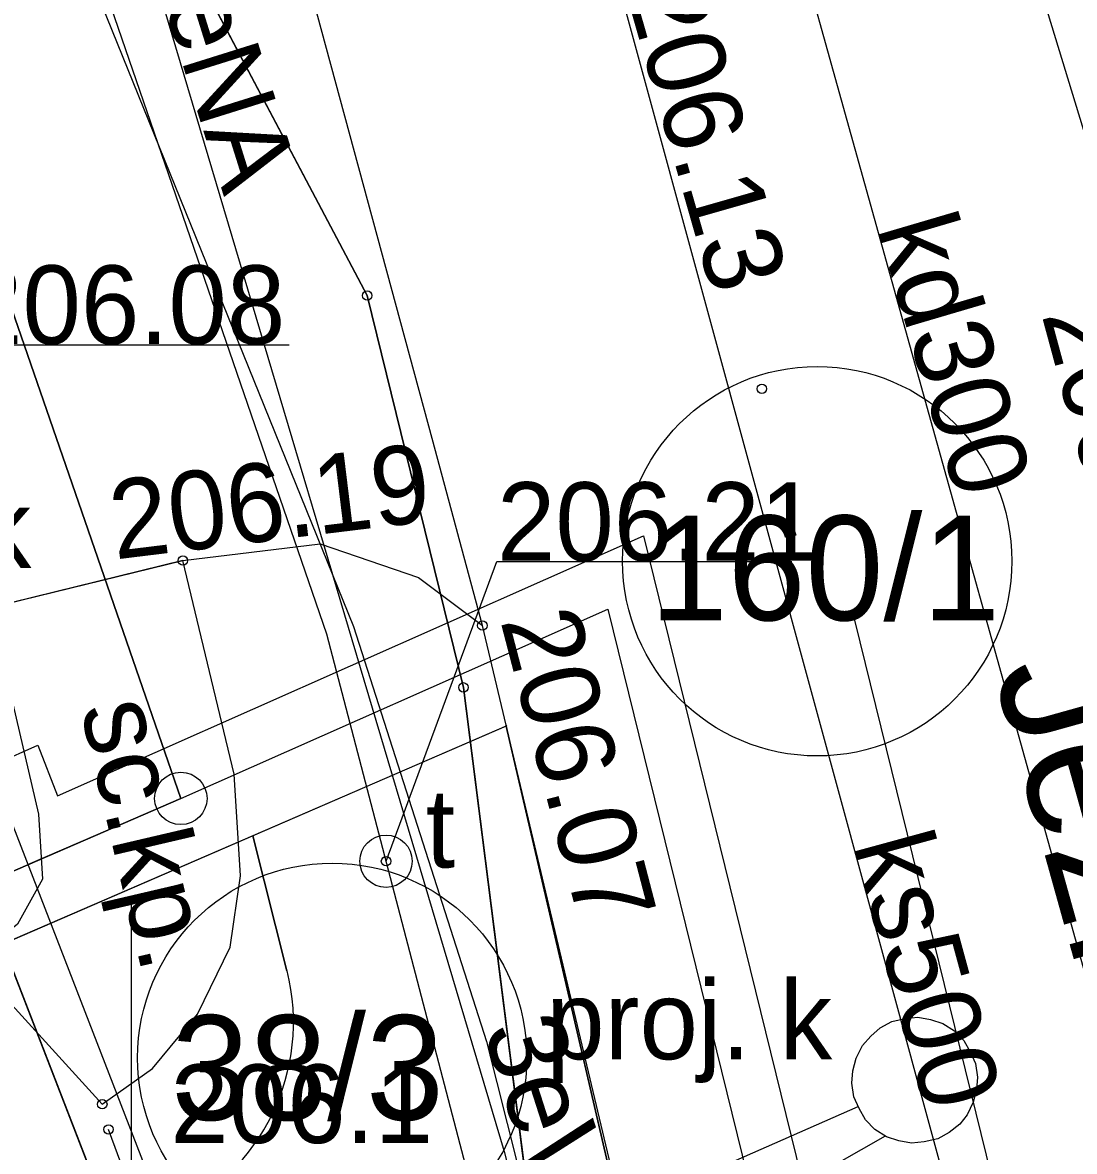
# Model space of a CAD drawing. Extents: x 6512606 to 6513006, y 6022524 to 6022728.
# Drawn here: x 6512848.96 to 6512859.01, y 6022600.08 to 6022610.86 of the extents above; entities that cross this region are included whole.
import ezdxf

# ---------------------------------------------------------------- set-up
doc = ezdxf.new("R2010")
doc.units = 0
for name, color, linetype in [('202-punkt graniczny', 7, 'Continuous'), ('203-punkt graniczny', 7, 'Continuous'), ('211-numer działki ewidencyjnej', 7, 'Continuous'), ('216-obręb ewidencyjny', 7, 'Continuous'), ('217-kontur klasyfikacyjny', 7, 'Continuous'), ('218-kontur użytku gruntowego', 7, 'Continuous'), ('219-działka ewidencyjna', 7, 'Continuous'), ('4', 7, 'Continuous'), ('6', 7, 'Continuous'), ('994-Nazwa ulicy', 7, 'Continuous'), ('Default', 7, 'Continuous'), ('jezdnia (powierzchnia)', 7, 'Continuous'), ('kolor_chodnik', 7, 'Continuous'), ('kolor_sc_rowerowa', 7, 'Continuous'), ('krawężnik (linia)', 7, 'Continuous'), ('maxp_kan_deszczowa', 7, 'Continuous'), ('maxp_kraw_nawierzchni', 7, 'Continuous'), ('maxp_os', 7, 'Continuous'), ('maxp_ramka_2', 7, 'Continuous'), ('ogrodzenie trwałe', 7, 'Continuous'), ('pikieta naturalna', 7, 'Continuous'), ('pikieta naturalna-Atr2', 7, 'Continuous'), ('pikieta sztuczna', 7, 'Continuous'), ('przewód elektroenergetyczny (linia)', 7, 'Continuous'), ('przewód elektroenergetyczny (linia)-Atr1', 7, 'Continuous'), ('przewód kanalizacyjny (linia)', 7, 'Continuous'), ('przewód kanalizacyjny (linia)-Atr1', 7, 'Continuous'), ('przewód kanalizacyjny - projektowany lub w budowie (linia) - ob. projektowany', 7, 'Continuous'), ('przewód telekomunikacyjny (linia)', 7, 'Continuous'), ('przewód wodociągowy (linia)', 7, 'Continuous'), ('punkt o określonej wysokości (sieć kanalizacyjna)-Atr2', 7, 'Continuous'), ('punkt o określonej wysokości (sieć telekomunikacyjna)', 7, 'Continuous'), ('punkt o określonej wysokości (sieć telekomunikacyjna)-Atr2', 7, 'Continuous'), ('punkt wysokościowy sztuczny', 7, 'Continuous'), ('punkt wysokościowy sztuczny-Atr2', 7, 'Continuous'), ('urządzenie techniczne projektowane lub w budowie (sieć kanalizacyjna) - powierzchnia - ob. projektowany', 7, 'Continuous'), ('urządzenie techniczne projektowane lub w budowie (sieć kanalizacyjna) - powierzchnia - ob. projektowany-Atr17', 7, 'Continuous'), ('właz okrągły - siec kanalizacyjna (punkt)-Atr17', 7, 'Continuous'), ('właz okrągły - siec telekomunikacyjna (punkt)', 7, 'Continuous'), ('właz okrągły - siec telekomunikacyjna (punkt)-Atr17', 7, 'Continuous'), ('ścieżka (powierzchnia)', 7, 'Continuous'), ('ścieżka (powierzchnia)-Atr17', 7, 'Continuous')]:
    doc.layers.add(name, color=color, linetype=linetype)

# ---------------------------------------------------------------- blocks, each defined once
blk = doc.blocks.new('203')
at = {"layer": 'Default'}
blk.add_circle((0, 0), 0.45, dxfattribs=at)
blk = doc.blocks.new('202')
at = {"layer": 'Default'}
blk.add_circle((0, 0), 2.5, dxfattribs=at)
blk = doc.blocks.new('US22')
at = {"layer": 'Default'}
blk.add_circle((0, 0), 2.5, dxfattribs=at)
blk = doc.blocks.new('PW01')
at = {"layer": 'Default'}
blk.add_circle((0, 0), 0.45, dxfattribs=at)
blk = doc.blocks.new('PW02')
at = {"layer": 'Default'}
blk.add_circle((0, 0), 0.45, dxfattribs=at)

msp = doc.modelspace()

# ---------------------------------------------------------------- linework, layer by layer
at = {"layer": '216-obręb ewidencyjny'}
for points in [[(6512836.687, 6022675.173), (6512833.61, 6022675.02), (6512828.67, 6022670.98), (6512801.96, 6022670.34), (6512810.18, 6022663.28), (6512825.37, 6022649.66), (6512838.47, 6022634.29), (6512852.25, 6022608.25), (6512853.17, 6022604.51), (6512855.78, 6022583.95), (6512858.85, 6022571.74), (6512828.23, 6022562.62), (6512818.47, 6022559.72), (6512824.714, 6022553.406)], [(6512728.286, 6022540.131), (6512737.69, 6022552.74), (6512751.08, 6022569.37), (6512775.81, 6022564.08), (6512780.7, 6022581.02), (6512806.2, 6022572.11), (6512806.62, 6022563.51), (6512811.41, 6022558.95), (6512818.47, 6022559.72), (6512828.23, 6022562.62), (6512858.85, 6022571.74), (6512855.78, 6022583.95), (6512853.17, 6022604.51), (6512852.25, 6022608.25), (6512838.47, 6022634.29)]]:
    msp.add_lwpolyline(points, dxfattribs=at)
at = {"layer": '217-kontur klasyfikacyjny'}
msp.add_lwpolyline([(6512855.78, 6022583.95), (6512848.55, 6022602.62)], dxfattribs=at)
at = {"layer": '218-kontur użytku gruntowego'}
for points in [[(6512852.25, 6022608.25), (6512838.47, 6022634.29)], [(6512838.47, 6022634.29), (6512852.25, 6022608.25)], [(6512850.47, 6022603.45), (6512842.84, 6022625.52)], [(6512842.84, 6022625.52), (6512850.47, 6022603.45)], [(6512853.17, 6022604.51), (6512852.25, 6022608.25)], [(6512852.25, 6022608.25), (6512853.17, 6022604.51)], [(6512855.78, 6022583.95), (6512853.17, 6022604.51)], [(6512853.17, 6022604.51), (6512855.78, 6022583.95)], [(6512848.55, 6022602.62), (6512850.47, 6022603.45)], [(6512850.47, 6022603.45), (6512848.55, 6022602.62)], [(6512848.55, 6022602.62), (6512855.78, 6022583.95)], [(6512855.78, 6022583.95), (6512848.55, 6022602.62)]]:
    msp.add_lwpolyline(points, dxfattribs=at)
at = {"layer": '219-działka ewidencyjna'}
for points in [[(6512838.47, 6022634.29), (6512852.25, 6022608.25)], [(6512842.84, 6022625.52), (6512850.47, 6022603.45)], [(6512853.17, 6022604.51), (6512852.25, 6022608.25)], [(6512855.78, 6022583.95), (6512853.17, 6022604.51)], [(6512850.47, 6022603.45), (6512848.55, 6022602.62)], [(6512855.78, 6022583.95), (6512848.55, 6022602.62)]]:
    msp.add_lwpolyline(points, dxfattribs=at)
at = {"layer": '4'}
for points in [[(6512838.47, 6022634.29), (6512852.25, 6022608.25)], [(6512842.84, 6022625.52), (6512850.47, 6022603.45)], [(6512853.17, 6022604.51), (6512852.25, 6022608.25)], [(6512855.78, 6022583.95), (6512853.17, 6022604.51)], [(6512850.47, 6022603.45), (6512848.55, 6022602.62)], [(6512855.78, 6022583.95), (6512848.55, 6022602.62)]]:
    msp.add_lwpolyline(points, dxfattribs=at)
at = {"layer": '6'}
for centre in [(6512856.549, 6022605.714), (6512851.916, 6022600.973)]:
    msp.add_circle(centre, 1.859, dxfattribs=at)
at = {"layer": 'Default'}
msp.add_line((6512850, 6022597.5), (6512850, 6022602.5), dxfattribs=at)
at = {"layer": 'jezdnia (powierzchnia)'}
msp.add_lwpolyline([(6512850.75, 6022614.71), (6512850.26, 6022613.71), (6512849.8, 6022613.04), (6512849.09, 6022612.33), (6512848.25, 6022611.75), (6512847.02, 6022611.04), (6512845.61, 6022610.5), (6512847.59, 6022605.11), (6512848.64, 6022605.27), (6512850.49, 6022605.72), (6512851.8, 6022605.88), (6512852.74, 6022605.56), (6512853.35, 6022605.1), (6512852.88, 6022606.85)], close=True, dxfattribs=at)
at = {"layer": 'kolor_chodnik'}
for p, q in [((6512853.578, 6022604.141), (6512851.157, 6022603.094)), ((6512854.975, 6022598.118), (6512853.578, 6022604.141)), ((6512851.157, 6022603.094), (6512851.484, 6022601.804))]:
    msp.add_line(p, q, dxfattribs=at)
msp.add_arc((6512849.546, 6022601.311), 2, 293.9, 14.2544, dxfattribs=at)
at = {"layer": 'kolor_sc_rowerowa'}
for p, q in [((6512851.157, 6022603.094), (6512848.767, 6022602.06)), ((6512851.484, 6022601.804), (6512851.157, 6022603.094))]:
    msp.add_line(p, q, dxfattribs=at)
msp.add_arc((6512849.546, 6022601.311), 2, 293.9, 14.2544, dxfattribs=at)
at = {"layer": 'krawężnik (linia)'}
msp.add_lwpolyline([(6512858.01, 6022586.22), (6512857.23, 6022588.81), (6512855.05, 6022597.75), (6512854.71, 6022599.38), (6512853.35, 6022605.1)], dxfattribs=at)
at = {"layer": 'maxp_kan_deszczowa'}
msp.add_lwpolyline([(6512851.482, 6022595.049), (6512848.64, 6022602.387), (6512844.992, 6022600.824), (6512840.035, 6022598.38)], dxfattribs=at)
at = {"layer": 'maxp_kraw_nawierzchni'}
for p, q in [((6512848.767, 6022602.06), (6512853.586, 6022604.145)), ((6512853.578, 6022604.141), (6512854.975, 6022598.118)), ((6512851.157, 6022603.094), (6512851.484, 6022601.804))]:
    msp.add_line(p, q, dxfattribs=at)
msp.add_arc((6512849.546, 6022601.311), 2, 293.9, 14.2544, dxfattribs=at)
at = {"layer": 'maxp_os'}
msp.add_line((6512856.906, 6022605.15), (6512862.491, 6022582.465), dxfattribs=at)
at = {"layer": 'maxp_ramka_2'}
for p, q in [((6512849.291, 6022603.475), (6512854.891, 6022605.956)), ((6512854.891, 6022605.956), (6512860.654, 6022582.548)), ((6512850.47, 6022603.45), (6512854.549, 6022605.257)), ((6512854.549, 6022605.257), (6512860.068, 6022582.835)), ((6512819.784, 6022590.966), (6512849.104, 6022603.959)), ((6512849.104, 6022603.959), (6512849.291, 6022603.475)), ((6512848.827, 6022603.29), (6512856.423, 6022583.675))]:
    msp.add_line(p, q, dxfattribs=at)
msp.add_lwpolyline([(6512849.009, 6022602.819), (6512850.47, 6022603.45)], dxfattribs=at)
at = {"layer": 'ogrodzenie trwałe'}
msp.add_lwpolyline([(6512851.8, 6022594.83), (6512849.78, 6022600.29)], dxfattribs=at)
at = {"layer": 'przewód elektroenergetyczny (linia)'}
for points in [[(6512802.27, 6022673.66), (6512807.42, 6022670.09), (6512811.38, 6022666.87), (6512814.66, 6022663.43), (6512826.4, 6022651.65), (6512827.82, 6022650.09), (6512834.03, 6022642.46), (6512842.84, 6022631.19), (6512844.67, 6022626.95), (6512847.57, 6022619.87), (6512849.81, 6022612.67), (6512853.56, 6022600.08), (6512856.46, 6022588.83), (6512861.26, 6022569.82), (6512861.768, 6022567.654)], [(6512847.6, 6022616.23), (6512852.12, 6022605.09), (6512853.39, 6022601.13), (6512855.57, 6022592.48), (6512858.1, 6022582.86), (6512868.09, 6022584.49), (6512870.03, 6022584.23), (6512871.36, 6022584.34), (6512875.65, 6022585.56)]]:
    msp.add_lwpolyline(points, dxfattribs=at)
at = {"layer": 'przewód kanalizacyjny (linia)'}
for points in [[(6512860.32, 6022597.43), (6512854.34, 6022618.87)], [(6512861.16, 6022586.16), (6512858.32, 6022597.78), (6512853.7, 6022614.72)]]:
    msp.add_lwpolyline(points, dxfattribs=at)
at = {"layer": 'przewód kanalizacyjny - projektowany lub w budowie (linia) - ob. projektowany'}
for points in [[(6512849.73, 6022597.34), (6512856.94, 6022600.51)], [(6512851.27, 6022593.61), (6512852.18, 6022597.37), (6512857.2, 6022600.23)]]:
    msp.add_lwpolyline(points, dxfattribs=at)
at = {"layer": 'przewód telekomunikacyjny (linia)'}
msp.add_lwpolyline([(6512836.6, 6022638.32), (6512844.42, 6022625.21), (6512848.91, 6022613.6), (6512851.86, 6022605.02), (6512853.91, 6022597.19), (6512860.14, 6022571.94), (6512860.33, 6022571.18)], dxfattribs=at)
at = {"layer": 'przewód wodociągowy (linia)'}
msp.add_lwpolyline([(6512859.28, 6022609.22), (6512855.66, 6022621.07)], dxfattribs=at)
at = {"layer": 'punkt o określonej wysokości (sieć kanalizacyjna)-Atr2'}
msp.add_lwpolyline([(6512847.74, 6022606.78), (6512848.4, 6022607.78), (6512851.504, 6022607.78)], dxfattribs=at)
at = {"layer": 'punkt o określonej wysokości (sieć telekomunikacyjna)-Atr2'}
msp.add_lwpolyline([(6512852.43, 6022602.85), (6512853.49, 6022605.71), (6512856.307, 6022605.71)], dxfattribs=at)
at = {"layer": 'urządzenie techniczne projektowane lub w budowie (sieć kanalizacyjna) - powierzchnia - ob. projektowany'}
msp.add_lwpolyline([(6512857.91, 6022600.34), (6512857.81, 6022600.26), (6512857.7, 6022600.2), (6512857.57, 6022600.17), (6512857.45, 6022600.16), (6512857.33, 6022600.18), (6512857.21, 6022600.22), (6512857.1, 6022600.29), (6512857.01, 6022600.38), (6512856.95, 6022600.49), (6512856.9, 6022600.6), (6512856.88, 6022600.73), (6512856.89, 6022600.85), (6512856.92, 6022600.97), (6512856.98, 6022601.09), (6512857.06, 6022601.18), (6512857.15, 6022601.26), (6512857.26, 6022601.32), (6512857.39, 6022601.35), (6512857.51, 6022601.36), (6512857.63, 6022601.34), (6512857.75, 6022601.3), (6512857.86, 6022601.23), (6512857.95, 6022601.14), (6512858.01, 6022601.03), (6512858.06, 6022600.92), (6512858.08, 6022600.79), (6512858.07, 6022600.67), (6512858.04, 6022600.55), (6512857.98, 6022600.43)], close=True, dxfattribs=at)
at = {"layer": 'ścieżka (powierzchnia)'}
msp.add_lwpolyline([(6512848.65, 6022605.27), (6512849.11, 6022603.3), (6512849.15, 6022602.68), (6512848.91, 6022602.25), (6512848.47, 6022601.9), (6512849.72, 6022600.53), (6512850.2, 6022600.87), (6512850.63, 6022601.39), (6512850.94, 6022602.03), (6512851.04, 6022602.71), (6512850.98, 6022603.68), (6512850.49, 6022605.72)], close=True, dxfattribs=at)

# ---------------------------------------------------------------- block references
at = {"layer": '202-punkt graniczny', "xscale": 0.1, "yscale": 0.10000000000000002}
msp.add_blockref('202', (6512850.47, 6022603.45), dxfattribs=at)
at = {"layer": '203-punkt graniczny', "xscale": 0.1, "yscale": 0.10000000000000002}
for p in [(6512852.25, 6022608.25), (6512853.17, 6022604.51)]:
    msp.add_blockref('203', p, dxfattribs=at)
at = {"layer": 'pikieta naturalna', "xscale": 0.1, "yscale": 0.10000000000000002}
msp.add_blockref('PW01', (6512849.78, 6022600.29), dxfattribs=at)
at = {"layer": 'pikieta sztuczna', "xscale": 0.1, "yscale": 0.10000000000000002}
msp.add_blockref('PW01', (6512849.72, 6022600.53), dxfattribs=at)
at = {"layer": 'punkt o określonej wysokości (sieć telekomunikacyjna)', "xscale": 0.10000000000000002, "yscale": 0.1, "rotation": -75.328}
msp.add_blockref('PW01', (6512852.43, 6022602.85), dxfattribs=at)
at = {"layer": 'punkt wysokościowy sztuczny', "xscale": 0.1, "yscale": 0.10000000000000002}
for p in [(6512856.02, 6022607.36), (6512850.49, 6022605.72), (6512853.35, 6022605.1)]:
    msp.add_blockref('PW02', p, dxfattribs=at)
at = {"layer": 'właz okrągły - siec telekomunikacyjna (punkt)', "xscale": 0.10000000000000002, "yscale": 0.1, "rotation": -75.328}
msp.add_blockref('US22', (6512852.43, 6022602.85), dxfattribs=at)

# ---------------------------------------------------------------- texts
at = {"layer": '211-numer działki ewidencyjnej'}
for s, p in [('160/1', (6512854.95, 6022605.15)), ('38/3', (6512850.38, 6022600.38))]:
    msp.add_text(s, height=1, dxfattribs=at).set_placement(p)
at = {"layer": '4'}
for s, p in [('160/1', (6512854.95, 6022605.15)), ('38/3', (6512850.38, 6022600.38))]:
    msp.add_text(s, height=1, dxfattribs=at).set_placement(p)
at = {"layer": '994-Nazwa ulicy'}
msp.add_text('Jeziorna', height=1.25, rotation=285.602, dxfattribs=at).set_placement((6512858.23, 6022604.67))
at = {"layer": 'pikieta naturalna-Atr2'}
msp.add_text('206.1', height=0.75, dxfattribs=at).set_placement((6512850.37, 6022600.16))
at = {"layer": 'przewód elektroenergetyczny (linia)-Atr1'}
for s, rotation, p in [('eNA', 287.392, (6512850.3, 6022611.05)), ('3eW', 287.781, (6512853.35, 6022601.24))]:
    msp.add_text(s, height=0.75, rotation=rotation, dxfattribs=at).set_placement(p)
at = {"layer": 'przewód kanalizacyjny (linia)-Atr1'}
for s, rotation, p in [('kd300', 286.402, (6512857.12, 6022608.9)), ('ks500', 285.255, (6512856.89, 6022603.01))]:
    msp.add_text(s, height=0.75, rotation=rotation, dxfattribs=at).set_placement(p)
at = {"layer": 'punkt o określonej wysokości (sieć kanalizacyjna)-Atr2'}
msp.add_text('206.08', height=0.75, dxfattribs=at).set_placement((6512848.4, 6022607.788))
at = {"layer": 'punkt o określonej wysokości (sieć telekomunikacyjna)-Atr2'}
msp.add_text('206.21', height=0.75, dxfattribs=at).set_placement((6512853.49, 6022605.718))
at = {"layer": 'punkt wysokościowy sztuczny-Atr2'}
for s, rotation, p in [('206.13', 285.965, (6512854.71, 6022611.18)), ('206.22', 285.164, (6512858.69, 6022608.07)), ('206.19', 6.963, (6512849.84, 6022605.73)), ('206.07', 284.642, (6512853.52, 6022605.15))]:
    msp.add_text(s, height=0.75, rotation=rotation, dxfattribs=at).set_placement(p)
at = {"layer": 'urządzenie techniczne projektowane lub w budowie (sieć kanalizacyjna) - powierzchnia - ob. projektowany-Atr17'}
msp.add_text('proj. k', height=0.75, dxfattribs=at).set_placement((6512853.96, 6022600.96))
at = {"layer": 'właz okrągły - siec kanalizacyjna (punkt)-Atr17'}
msp.add_text('k', height=0.75, dxfattribs=at).set_placement((6512848.54, 6022605.65))
at = {"layer": 'właz okrągły - siec telekomunikacyjna (punkt)-Atr17'}
msp.add_text('t', height=0.75, dxfattribs=at).set_placement((6512852.81, 6022602.79))
at = {"layer": 'ścieżka (powierzchnia)-Atr17'}
msp.add_text('sc.kp.', height=0.75, rotation=283.143, dxfattribs=at).set_placement((6512849.51, 6022604.31))

doc.saveas('drawing.dxf')
